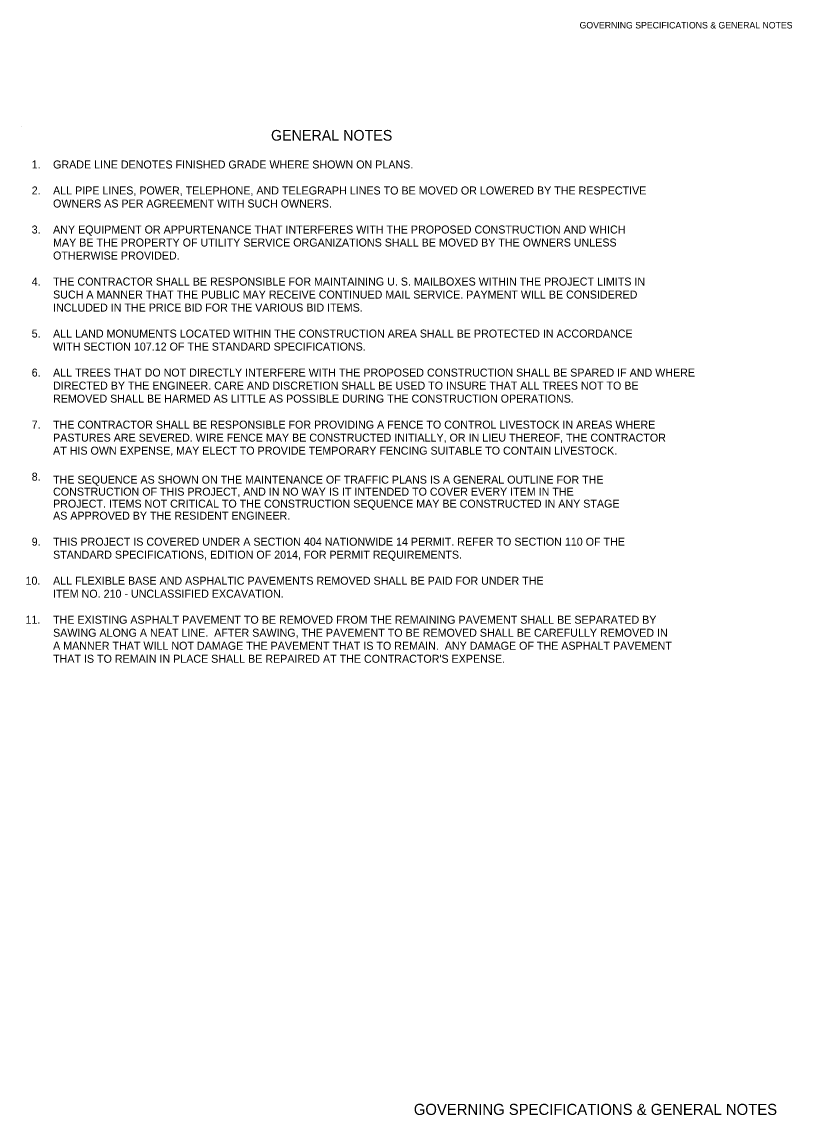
# Model space of a CAD drawing. Extents: x 1.5 to 33, y 0.6 to 21.4.
# Drawn here: x 19.18 to 33.04, y 0.69 to 20.36 of the extents above; entities that cross this region are included whole.
import ezdxf

# ---------------------------------------------------------------- set-up
doc = ezdxf.new("R2010")
doc.units = 0
for name, color, linetype in [('Default', 7, 'Continuous'), ('R_Annotation', 7, 'Continuous'), ('R_Border', 7, 'Continuous')]:
    doc.layers.add(name, color=color, linetype=linetype)

msp = doc.modelspace()

# ---------------------------------------------------------------- linework, layer by layer
at = {"layer": 'Default'}
msp.add_line((19.178, 18.48), (19.178, 18.48), dxfattribs=at)

# ---------------------------------------------------------------- texts
for s, height, p in [('GENERAL NOTES', 0.192, (23.663, 18.226)), ('1.', 0.144, (19.355, 17.725)), ('GRADE LINE DENOTES FINISHED GRADE WHERE SHOWN ON PLANS.', 0.144, (19.74, 17.725)), ('2.', 0.144, (19.355, 17.257)), ('ALL PIPE LINES, POWER, TELEPHONE, AND TELEGRAPH LINES TO BE MOVED OR LOWERED BY THE RESPECTIVE ', 0.144, (19.74, 17.257)), ('OWNERS AS PER AGREEMENT WITH SUCH OWNERS.', 0.144, (19.74, 17.023)), ('3.', 0.144, (19.355, 16.555)), ('ANY EQUIPMENT OR APPURTENANCE THAT INTERFERES WITH THE PROPOSED CONSTRUCTION AND WHICH ', 0.144, (19.74, 16.555)), ('MAY BE THE PROPERTY OF UTILITY SERVICE ORGANIZATIONS SHALL BE MOVED BY THE OWNERS UNLESS ', 0.144, (19.74, 16.321)), ('OTHERWISE PROVIDED.', 0.144, (19.74, 16.087)), ('4.', 0.144, (19.355, 15.619)), ('THE CONTRACTOR SHALL BE RESPONSIBLE FOR MAINTAINING U. S. MAILBOXES WITHIN THE PROJECT LIMITS IN ', 0.144, (19.74, 15.619)), ('SUCH A MANNER THAT THE PUBLIC MAY RECEIVE CONTINUED MAIL SERVICE. PAYMENT WILL BE CONSIDERED ', 0.144, (19.74, 15.385)), ('INCLUDED IN THE PRICE BID FOR THE VARIOUS BID ITEMS.', 0.144, (19.74, 15.151)), ('5.', 0.144, (19.355, 14.683)), ('ALL LAND MONUMENTS LOCATED WITHIN THE CONSTRUCTION AREA SHALL BE PROTECTED IN ACCORDANCE ', 0.144, (19.74, 14.683)), ('WITH SECTION 107.12 OF THE STANDARD SPECIFICATIONS.', 0.144, (19.74, 14.449)), ('6.', 0.144, (19.355, 13.981)), ('ALL TREES THAT DO NOT DIRECTLY INTERFERE WITH THE PROPOSED CONSTRUCTION SHALL BE SPARED IF AND WHERE ', 0.144, (19.74, 13.981)), ('DIRECTED BY THE ENGINEER. CARE AND DISCRETION SHALL BE USED TO INSURE THAT ALL TREES NOT TO BE ', 0.144, (19.74, 13.747)), ('REMOVED SHALL BE HARMED AS LITTLE AS POSSIBLE DURING THE CONSTRUCTION OPERATIONS.', 0.144, (19.74, 13.513)), ('7.', 0.144, (19.355, 13.045)), ('THE CONTRACTOR SHALL BE RESPONSIBLE FOR PROVIDING A FENCE TO CONTROL LIVESTOCK IN AREAS WHERE ', 0.144, (19.74, 13.045)), ('PASTURES ARE SEVERED. WIRE FENCE MAY BE CONSTRUCTED INITIALLY, OR IN LIEU THEREOF, THE CONTRACTOR ', 0.144, (19.74, 12.811)), ('AT HIS OWN EXPENSE, MAY ELECT TO PROVIDE TEMPORARY FENCING SUITABLE TO CONTAIN LIVESTOCK.', 0.144, (19.74, 12.577)), ('8.', 0.144, (19.355, 12.109)), ('THE SEQUENCE AS SHOWN ON THE MAINTENANCE OF TRAFFIC PLANS IS A GENERAL OUTLINE FOR THE', 0.144, (19.74, 12.055)), ('CONSTRUCTION OF THIS PROJECT, AND IN NO WAY IS IT INTENDED TO COVER EVERY ITEM IN THE', 0.144, (19.74, 11.839)), ('PROJECT. ITEMS NOT CRITICAL TO THE CONSTRUCTION SEQUENCE MAY BE CONSTRUCTED IN ANY STAGE', 0.144, (19.74, 11.623)), ('AS APPROVED BY THE RESIDENT ENGINEER.', 0.144, (19.74, 11.407)), ('9.', 0.144, (19.355, 10.939)), ('THIS PROJECT IS COVERED UNDER A SECTION 404 NATIONWIDE 14 PERMIT. REFER TO SECTION 110 OF THE ', 0.144, (19.74, 10.939)), ('STANDARD SPECIFICATIONS, EDITION OF 2014, FOR PERMIT REQUIREMENTS.', 0.144, (19.74, 10.705)), ('10.', 0.144, (19.244, 10.237)), ('ALL FLEXIBLE BASE AND ASPHALTIC PAVEMENTS REMOVED SHALL BE PAID FOR UNDER THE ', 0.144, (19.74, 10.237)), ('ITEM NO. 210 - UNCLASSIFIED EXCAVATION.', 0.144, (19.74, 10.003)), ('11.', 0.144, (19.244, 9.535)), ('THE EXISTING ASPHALT PAVEMENT TO BE REMOVED FROM THE REMAINING PAVEMENT SHALL BE SEPARATED BY ', 0.144, (19.74, 9.535)), ('SAWING ALONG A NEAT LINE.  AFTER SAWING, THE PAVEMENT TO BE REMOVED SHALL BE CAREFULLY REMOVED IN ', 0.144, (19.74, 9.301)), ('A MANNER THAT WILL NOT DAMAGE THE PAVEMENT THAT IS TO REMAIN.  ANY DAMAGE OF THE ASPHALT PAVEMENT ', 0.144, (19.74, 9.067)), ("THAT IS TO REMAIN IN PLACE SHALL BE REPAIRED AT THE CONTRACTOR'S EXPENSE.  ", 0.144, (19.74, 8.833))]:
    msp.add_text(s, height=height, dxfattribs=at).set_placement(p)
at = {"layer": 'R_Annotation'}
msp.add_text('GOVERNING SPECIFICATIONS & GENERAL NOTES', height=0.2, dxfattribs=at).set_placement((26.233, 0.698))
at = {"layer": 'R_Border'}
msp.add_text('GOVERNING SPECIFICATIONS & GENERAL NOTES', height=0.11724, dxfattribs=at).set_placement((29.217, 20.244))

doc.saveas('drawing.dxf')
